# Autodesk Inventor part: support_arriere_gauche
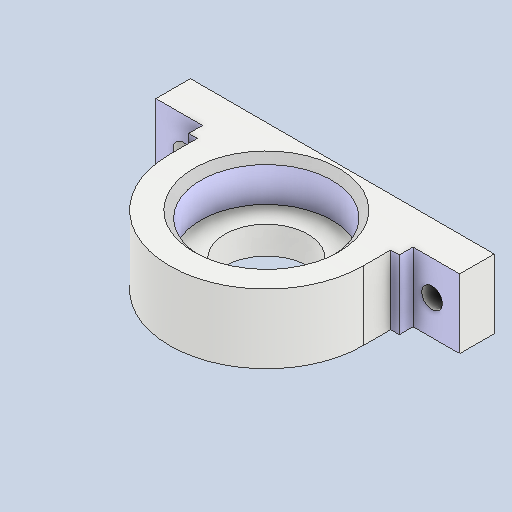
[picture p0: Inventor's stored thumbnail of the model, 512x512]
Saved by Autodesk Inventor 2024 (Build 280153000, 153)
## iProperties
Created: 2020-09
Part Number: support_arriere_gauche
Material: Genérico
Document SubType Name: Modeling
Designer: gasparoto
Density: 1 g/cm^3
Appearance: Padrão
Mass: 4.75353 g
Surface Area: 29.766 cm^2
Volume: 4.75353 cm^3
Author: gasparoto
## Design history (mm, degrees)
feature "Base1"
chamfer "Chanfrein1" distance "d0" = 1; stored, may be unused: second distance "d1" = 2, angle "d2" = 45 deg
node "Sólido1"
